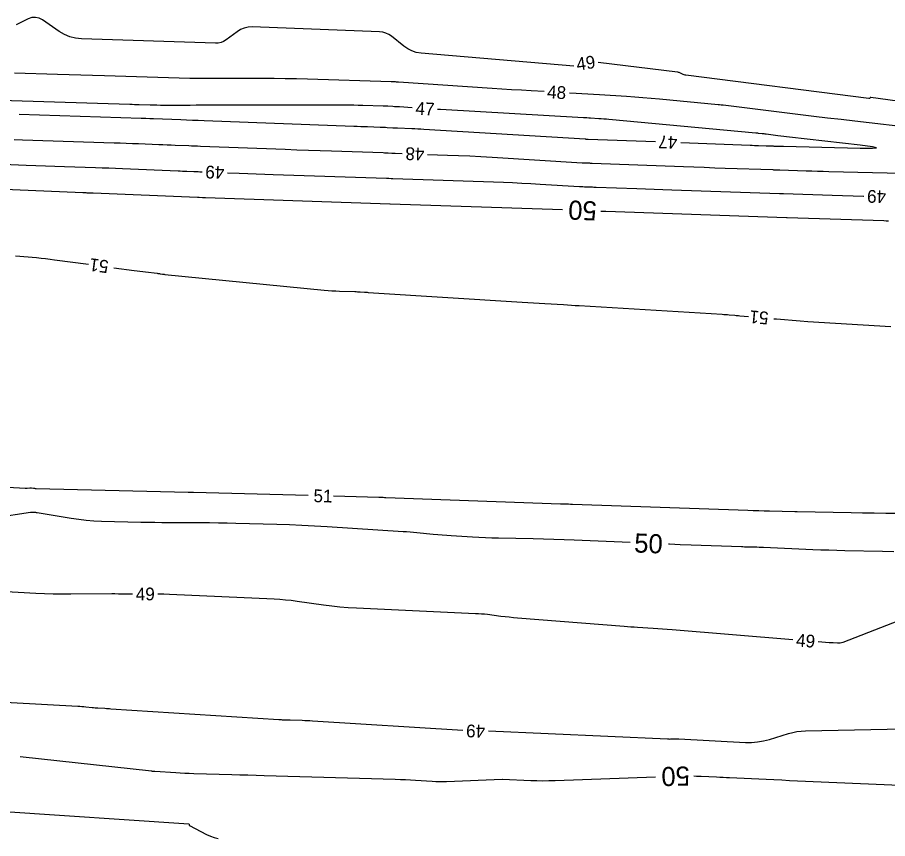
# Model space of a CAD drawing. Extents: x 2384780 to 2405861, y 547869 to 573706.
# Drawn here: x 2392231.5 to 2392368.2, y 552612.6 to 552741.6 of the extents above; entities that cross this region are included whole.
import ezdxf

# ---------------------------------------------------------------- set-up
doc = ezdxf.new("R2010")
doc.units = 0
doc.layers.add('Old_Level_60', color=7, linetype='Continuous')
doc.layers.add('Old_Level_61', color=7, linetype='Continuous')

msp = doc.modelspace()

# ---------------------------------------------------------------- linework, layer by layer
at = {"layer": 'Old_Level_60'}
for points in [[(2392318.946, 552733.94425), (2392294.92275, 552735.98225), (2392294.1865, 552736.098), (2392293.4915, 552736.3165), (2392292.8375, 552736.638), (2392292.22475, 552737.06225), (2392290.29025, 552738.616), (2392289.861, 552738.91), (2392289.40275, 552739.12575), (2392288.91525, 552739.26325), (2392288.3985, 552739.3225), (2392268.411, 552740.0835), (2392267.7685, 552740.05625), (2392267.1585, 552739.92475), (2392266.58075, 552739.68875), (2392266.03525, 552739.34825), (2392264.306, 552738.06525), (2392263.92425, 552737.82675), (2392263.51975, 552737.6605), (2392263.0925, 552737.567), (2392262.64275, 552737.54575), (2392241.6115, 552738.23625), (2392240.67325, 552738.3315), (2392239.77675, 552738.5545), (2392238.92225, 552738.9055), (2392238.1095, 552739.384), (2392235.48175, 552741.184), (2392234.94225, 552741.46825), (2392234.39075, 552741.59025), (2392233.8275, 552741.5495), (2392233.2525, 552741.34625), (2392231.35475, 552740.41675)], [(2392369.731, 552728.44225), (2392365.5835, 552729.002), (2392365.54375, 552729.0035), (2392365.50625, 552728.99725), (2392365.471, 552728.983), (2392365.438, 552728.961), (2392365.334, 552728.87575), (2392365.31075, 552728.86025), (2392365.28625, 552728.85025), (2392365.26, 552728.84575), (2392365.232, 552728.84675), (2392336.52225, 552732.51525), (2392336.382, 552732.53875), (2392336.245, 552732.573), (2392336.111, 552732.61825), (2392335.98025, 552732.674), (2392335.5585, 552732.874), (2392335.467, 552732.91275), (2392335.37325, 552732.94425), (2392335.27725, 552732.96775), (2392335.179, 552732.98375), (2392322.74, 552734.4965)], [(2392314.24625, 552729.93575), (2392312.199, 552730.05175), (2392310.679, 552730.13975), (2392309.1595, 552730.23175), (2392307.64025, 552730.32775), (2392306.121, 552730.42775), (2392291.4055, 552731.416), (2392291.28775, 552731.42375), (2392291.17025, 552731.43125), (2392291.0525, 552731.4385), (2392290.93475, 552731.44525), (2392290.55, 552731.467), (2392290.46775, 552731.47125), (2392290.38525, 552731.47525), (2392290.30275, 552731.4785), (2392290.22025, 552731.48125), (2392277.07925, 552731.87825), (2392275.3475, 552731.924), (2392273.61575, 552731.95625), (2392271.88375, 552731.975), (2392270.1515, 552731.98025), (2392262.928, 552731.97475), (2392262.4975, 552731.9745), (2392262.06725, 552731.97425), (2392261.63675, 552731.97375), (2392261.2065, 552731.9735), (2392259.8005, 552731.9725), (2392259.49925, 552731.9735), (2392259.19825, 552731.97675), (2392258.897, 552731.98225), (2392258.59575, 552731.99025), (2392245.204, 552732.3965), (2392243.36025, 552732.4525), (2392241.5165, 552732.50875), (2392239.673, 552732.565), (2392237.82925, 552732.62125), (2392231.0935, 552732.827)], [(2392293.51075, 552727.38425), (2392291.53, 552727.51725), (2392291.27875, 552727.53375), (2392291.0275, 552727.54975), (2392290.776, 552727.565), (2392290.5245, 552727.5795), (2392289.703, 552727.626), (2392289.527, 552727.63525), (2392289.35075, 552727.6435), (2392289.17475, 552727.6505), (2392288.9985, 552727.6565), (2392285.7645, 552727.75425), (2392285.0715, 552727.7725), (2392284.3785, 552727.78525), (2392283.68525, 552727.79275), (2392282.992, 552727.795), (2392261.4575, 552727.7785), (2392260.53475, 552727.77775), (2392259.61175, 552727.77725), (2392258.68875, 552727.7765), (2392257.76575, 552727.77575), (2392254.5175, 552727.77325), (2392253.98825, 552727.775), (2392253.459, 552727.78075), (2392252.92975, 552727.7905), (2392252.4005, 552727.8045), (2392250.67175, 552727.857), (2392250.3015, 552727.86825), (2392249.931, 552727.8795), (2392249.5605, 552727.89075), (2392249.19025, 552727.90225), (2392223.8225, 552728.67725)], [(2392372.96725, 552724.14875), (2392363.02575, 552725.288), (2392360.89575, 552725.53425), (2392358.76625, 552725.785), (2392356.63725, 552726.03975), (2392354.50875, 552726.299), (2392342.38, 552727.7885), (2392342.2995, 552727.7985), (2392342.219, 552727.808), (2392342.1385, 552727.8175), (2392342.058, 552727.827), (2392341.795, 552727.8575), (2392341.73875, 552727.86375), (2392341.68225, 552727.86975), (2392341.62575, 552727.8755), (2392341.56925, 552727.881), (2392332.37925, 552728.728), (2392331.081, 552728.8435), (2392329.78225, 552728.951), (2392328.48275, 552729.05), (2392327.1825, 552729.14125), (2392322.9345, 552729.42525), (2392322.024, 552729.485), (2392321.1135, 552729.54225), (2392320.20275, 552729.5975), (2392319.292, 552729.65), (2392318.23975, 552729.70975)], [(2392231.84125, 552726.37275), (2392250.9685, 552725.76425), (2392251.16, 552725.758), (2392251.35175, 552725.75125), (2392251.54325, 552725.74375), (2392251.735, 552725.736), (2392252.36075, 552725.70975), (2392252.495, 552725.70425), (2392252.629, 552725.69875), (2392252.76325, 552725.6935), (2392252.89725, 552725.6885), (2392257.1815, 552725.527), (2392258.0995, 552725.4925), (2392259.0175, 552725.458), (2392259.9355, 552725.4235), (2392260.8535, 552725.38875), (2392284.3775, 552724.50325), (2392284.91675, 552724.483), (2392285.456, 552724.4635), (2392285.9955, 552724.4445), (2392286.53475, 552724.42625), (2392288.50875, 552724.3595), (2392288.78025, 552724.3495), (2392289.0515, 552724.3375), (2392289.32275, 552724.32375), (2392289.594, 552724.30775), (2392290.4795, 552724.25325), (2392290.66925, 552724.24225), (2392290.859, 552724.2325), (2392291.049, 552724.22425), (2392291.239, 552724.217), (2392293.46525, 552724.142), (2392293.94225, 552724.12425), (2392294.419, 552724.10325), (2392294.89575, 552724.07875), (2392295.37225, 552724.05125), (2392320.71275, 552722.49325), (2392320.76, 552722.4905), (2392320.80725, 552722.488), (2392320.85425, 552722.486), (2392320.9015, 552722.48425), (2392321.05575, 552722.479), (2392321.08875, 552722.47775), (2392321.12175, 552722.47675), (2392321.15475, 552722.4755), (2392321.18775, 552722.47425), (2392331.742, 552722.07275)], [(2392335.73925, 552721.92075), (2392346.63, 552721.5065), (2392346.95125, 552721.4945), (2392347.2725, 552721.48275), (2392347.59375, 552721.4715), (2392347.915, 552721.4605), (2392349.102, 552721.42075), (2392349.25825, 552721.41575), (2392349.4145, 552721.411), (2392349.57075, 552721.40675), (2392349.727, 552721.40275), (2392350.2375, 552721.39025), (2392350.34675, 552721.3875), (2392350.45625, 552721.3845), (2392350.5655, 552721.38125), (2392350.67475, 552721.37775), (2392351.3125, 552721.35625), (2392351.44925, 552721.352), (2392351.58575, 552721.34775), (2392351.7225, 552721.344), (2392351.85925, 552721.34075), (2392363.88225, 552721.05475), (2392365.8165, 552721.03775), (2392366.4665, 552721.1095), (2392365.8325, 552721.27), (2392363.91425, 552721.519), (2392352.8065, 552722.79175), (2392352.34425, 552722.84525), (2392351.882, 552722.89975), (2392351.41975, 552722.955), (2392350.95775, 552723.01125), (2392349.12725, 552723.236), (2392348.9645, 552723.256), (2392348.80175, 552723.2755), (2392348.63875, 552723.29475), (2392348.47575, 552723.31375), (2392347.9435, 552723.3755), (2392347.8295, 552723.38825), (2392347.71525, 552723.4005), (2392347.601, 552723.412), (2392347.48675, 552723.423), (2392324.43025, 552725.548), (2392324.03225, 552725.5835), (2392323.634, 552725.6165), (2392323.2355, 552725.64675), (2392322.83675, 552725.67475), (2392321.53425, 552725.76175), (2392321.255, 552725.78025), (2392320.97575, 552725.79775), (2392320.69675, 552725.81475), (2392320.41725, 552725.83075), (2392297.97825, 552727.10125), (2392297.50275, 552727.12875)], [(2392231.04725, 552722.40725), (2392232.34875, 552722.36425), (2392246.716, 552721.90725), (2392247.67675, 552721.8755), (2392248.63725, 552721.84125), (2392249.59775, 552721.8045), (2392250.558, 552721.76525), (2392253.743, 552721.6315), (2392254.39125, 552721.60475), (2392255.0395, 552721.5785), (2392255.688, 552721.553), (2392256.33625, 552721.52825), (2392258.45425, 552721.4485), (2392258.908, 552721.4315), (2392259.362, 552721.41425), (2392259.81575, 552721.39725), (2392260.2695, 552721.38025), (2392273.6125, 552720.87775), (2392275.43125, 552720.81025), (2392277.25, 552720.7445), (2392279.06875, 552720.6805), (2392280.88775, 552720.61825), (2392289.00725, 552720.34425), (2392289.19175, 552720.3375), (2392289.37575, 552720.32925), (2392289.56, 552720.32), (2392289.74425, 552720.30925), (2392290.3455, 552720.272), (2392290.47425, 552720.26475), (2392290.60325, 552720.258), (2392290.73225, 552720.25225), (2392290.86125, 552720.2475), (2392291.95025, 552720.21075)], [(2392217.11775, 552719.0455), (2392232.93825, 552718.38325), (2392234.436, 552718.3225), (2392235.93425, 552718.26525), (2392237.43225, 552718.212), (2392238.93075, 552718.1625), (2392243.8255, 552718.00675), (2392244.87425, 552717.972), (2392245.923, 552717.93475), (2392246.97175, 552717.8945), (2392248.02025, 552717.852), (2392256.77325, 552717.484), (2392257.11175, 552717.47), (2392257.45, 552717.45625), (2392257.7885, 552717.443), (2392258.127, 552717.43), (2392259.2325, 552717.3885), (2392259.46925, 552717.3795), (2392259.70625, 552717.37075), (2392259.94325, 552717.36175), (2392260.18, 552717.35275), (2392260.5555, 552717.33875)], [(2392295.948, 552720.076), (2392299.067, 552719.97075), (2392300.825, 552719.90525), (2392302.5825, 552719.82775), (2392304.3395, 552719.738), (2392306.096, 552719.636), (2392320.25575, 552718.7655), (2392320.4095, 552718.7565), (2392320.56325, 552718.74875), (2392320.71725, 552718.742), (2392320.871, 552718.73625), (2392321.37375, 552718.71925), (2392321.4815, 552718.7155), (2392321.58925, 552718.7115), (2392321.697, 552718.70775), (2392321.80475, 552718.70375), (2392336.12025, 552718.15925), (2392337.7665, 552718.0975), (2392339.4125, 552718.03775), (2392341.05875, 552717.97975), (2392342.705, 552717.92375), (2392350.172, 552717.67375), (2392350.27975, 552717.6705), (2392350.38775, 552717.66725), (2392350.49575, 552717.66425), (2392350.6035, 552717.6615), (2392350.956, 552717.65275), (2392351.0315, 552717.65075), (2392351.107, 552717.64875), (2392351.1825, 552717.6465), (2392351.258, 552717.644), (2392355.40075, 552717.5055), (2392356.28825, 552717.47675), (2392357.176, 552717.45025), (2392358.064, 552717.426), (2392358.95175, 552717.40375), (2392374.98775, 552717.0225)], [(2392264.5525, 552717.18825), (2392266.3845, 552717.11925), (2392267.714, 552717.06975), (2392269.0435, 552717.02175), (2392270.37325, 552716.975), (2392271.703, 552716.9295), (2392289.506, 552716.329), (2392289.603, 552716.3255), (2392289.70025, 552716.321), (2392289.79725, 552716.31625), (2392289.8945, 552716.3105), (2392290.2115, 552716.291), (2392290.27925, 552716.287), (2392290.34725, 552716.2835), (2392290.41525, 552716.2805), (2392290.48325, 552716.278), (2392307.873, 552715.69125), (2392309.3105, 552715.63775), (2392310.74725, 552715.5745), (2392312.1835, 552715.501), (2392313.6195, 552715.41775), (2392319.79875, 552715.03775), (2392320.059, 552715.02275), (2392320.3195, 552715.0095), (2392320.58, 552714.998), (2392320.8405, 552714.98825), (2392321.692, 552714.95925), (2392321.8745, 552714.953), (2392322.05675, 552714.9465), (2392322.23925, 552714.94), (2392322.42175, 552714.933), (2392328.81325, 552714.69), (2392330.18275, 552714.63875), (2392331.5525, 552714.589), (2392332.92225, 552714.54075), (2392334.292, 552714.494), (2392351.24175, 552713.927), (2392351.3015, 552713.925), (2392351.361, 552713.92325), (2392351.4205, 552713.9215), (2392351.48, 552713.92), (2392351.6745, 552713.91525), (2392351.71625, 552713.91425), (2392351.758, 552713.913), (2392351.79975, 552713.91175), (2392351.84125, 552713.9105), (2392359.48875, 552713.6545), (2392361.1275, 552713.60175), (2392362.7665, 552713.55275), (2392364.4055, 552713.508), (2392364.4815, 552713.506)], [(2392231.24525, 552704.1535), (2392234.54925, 552703.848), (2392235.25675, 552703.77875), (2392235.9635, 552703.70225), (2392236.6695, 552703.6185), (2392237.37475, 552703.5275), (2392242.7235, 552702.808)], [(2392246.688, 552702.275), (2392249.88675, 552701.84475), (2392250.3295, 552701.78575), (2392250.7725, 552701.7285), (2392251.21575, 552701.6725), (2392251.659, 552701.618), (2392253.4935, 552701.39575), (2392253.611, 552701.38075), (2392253.72825, 552701.3645), (2392253.84525, 552701.34725), (2392253.96225, 552701.3285), (2392254.34375, 552701.265), (2392254.4255, 552701.252), (2392254.50775, 552701.2405), (2392254.58975, 552701.2305), (2392254.67225, 552701.22175), (2392279.71925, 552698.76), (2392280.31975, 552698.70575), (2392280.921, 552698.661), (2392281.52275, 552698.6255), (2392282.12525, 552698.5995), (2392284.521, 552698.51525), (2392284.7295, 552698.50725), (2392284.93825, 552698.49775), (2392285.14675, 552698.48725), (2392285.35525, 552698.47525), (2392286.036, 552698.434), (2392286.182, 552698.425), (2392286.328, 552698.416), (2392286.47375, 552698.407), (2392286.61975, 552698.39775), (2392310.8225, 552696.86725), (2392311.712, 552696.8115), (2392312.60175, 552696.756), (2392313.49125, 552696.70125), (2392314.381, 552696.64725), (2392317.28725, 552696.47125), (2392317.91, 552696.4335), (2392318.533, 552696.39575), (2392319.15575, 552696.35775), (2392319.7785, 552696.32), (2392342.22075, 552694.95325), (2392342.49475, 552694.9355), (2392342.76875, 552694.916), (2392343.04275, 552694.89475), (2392343.3165, 552694.8715), (2392344.21025, 552694.79275), (2392344.402, 552694.77575), (2392344.5935, 552694.75875), (2392344.785, 552694.742), (2392344.9765, 552694.725), (2392346.3655, 552694.6025)], [(2392350.35, 552694.25125), (2392350.7455, 552694.21625), (2392351.982, 552694.11125), (2392353.21925, 552694.0145), (2392354.457, 552693.9255), (2392355.69525, 552693.84475), (2392368.702, 552693.038)], [(2392277.1785, 552666.47575), (2392259.21875, 552666.9365), (2392259.135, 552666.9385), (2392259.0515, 552666.94), (2392258.96775, 552666.941), (2392258.884, 552666.9415), (2392258.6105, 552666.94275), (2392258.552, 552666.94325), (2392258.4935, 552666.944), (2392258.43475, 552666.945), (2392258.37625, 552666.94625), (2392234.46875, 552667.55475), (2392234.37175, 552667.559), (2392234.275, 552667.5665), (2392234.1785, 552667.5775), (2392234.0825, 552667.592), (2392233.769, 552667.6445), (2392233.70175, 552667.653), (2392233.6345, 552667.6565), (2392233.56725, 552667.65475), (2392233.49975, 552667.6475), (2392233.09925, 552667.59025), (2392233.0135, 552667.58), (2392232.92725, 552667.57425), (2392232.841, 552667.57275), (2392232.7545, 552667.5755), (2392203.68075, 552669.25225)], [(2392369.75775, 552663.664), (2392367.93125, 552663.67825), (2392366.105, 552663.6985), (2392364.27875, 552663.725), (2392362.4525, 552663.75725), (2392354.0095, 552663.9215), (2392353.97, 552663.92225), (2392353.9305, 552663.9235), (2392353.89125, 552663.92475), (2392353.85175, 552663.9265), (2392353.72325, 552663.93225), (2392353.69575, 552663.93325), (2392353.668, 552663.93425), (2392353.6405, 552663.935), (2392353.613, 552663.93575), (2392349.65525, 552664.01475), (2392348.80725, 552664.03325), (2392347.95925, 552664.05525), (2392347.11125, 552664.08025), (2392346.2635, 552664.10875), (2392318.73125, 552665.085), (2392318.64525, 552665.08825), (2392318.55925, 552665.0915), (2392318.473, 552665.095), (2392318.387, 552665.09875), (2392318.106, 552665.11125), (2392318.046, 552665.11375), (2392317.98575, 552665.11575), (2392317.9255, 552665.11725), (2392317.86525, 552665.1185), (2392317.29925, 552665.1285), (2392317.17775, 552665.13075), (2392317.0565, 552665.13375), (2392316.93525, 552665.13725), (2392316.814, 552665.14125), (2392289.42425, 552666.1135), (2392289.36625, 552666.11625), (2392289.30825, 552666.1195), (2392289.2505, 552666.12375), (2392289.1925, 552666.129), (2392289.00375, 552666.14775), (2392288.96325, 552666.1515), (2392288.923, 552666.155), (2392288.88225, 552666.158), (2392288.84175, 552666.16075), (2392288.561, 552666.179), (2392288.50075, 552666.18275), (2392288.4405, 552666.18575), (2392288.38025, 552666.188), (2392288.32, 552666.19), (2392281.17725, 552666.37325)], [(2392249.62075, 552650.99475), (2392248.08575, 552650.97975), (2392247.91575, 552650.97925), (2392247.74575, 552650.98125), (2392247.576, 552650.9855), (2392247.40625, 552650.992), (2392246.85175, 552651.0175), (2392246.73275, 552651.02225), (2392246.614, 552651.02525), (2392246.495, 552651.0265), (2392246.376, 552651.02625), (2392239.93825, 552650.96475), (2392238.559, 552650.96325), (2392237.1805, 552650.9845), (2392235.80225, 552651.02875), (2392234.42475, 552651.096), (2392218.6555, 552651.99725)], [(2392353.327, 552643.83475), (2392334.34125, 552645.38575), (2392333.5975, 552645.4445), (2392332.8535, 552645.49975), (2392332.10925, 552645.551), (2392331.36475, 552645.59875), (2392328.9325, 552645.748), (2392328.41125, 552645.78125), (2392327.89025, 552645.817), (2392327.3695, 552645.855), (2392326.84875, 552645.8955), (2392310.089, 552647.23525), (2392309.43375, 552647.29125), (2392308.779, 552647.3545), (2392308.125, 552647.425), (2392307.472, 552647.5025), (2392305.3395, 552647.768), (2392304.882, 552647.82025), (2392304.424, 552647.86375), (2392303.965, 552647.898), (2392303.5055, 552647.92325), (2392284.77575, 552648.771), (2392283.48575, 552648.845), (2392282.19875, 552648.95025), (2392280.91475, 552649.0865), (2392279.6335, 552649.254), (2392275.453, 552649.852), (2392274.556, 552649.96925), (2392273.65725, 552650.065), (2392272.75625, 552650.13925), (2392271.85325, 552650.19175), (2392255.4115, 552650.95175), (2392254.52775, 552650.9865), (2392253.6435, 552651.00875), (2392253.62075, 552651.009)], [(2392375.815, 552649.12325), (2392361.17425, 552643.41075), (2392360.9715, 552643.34375), (2392360.76525, 552643.3), (2392360.5555, 552643.279), (2392360.342, 552643.281), (2392359.639, 552643.325), (2392359.4885, 552643.33475), (2392359.338, 552643.34525), (2392359.1875, 552643.3565), (2392359.037, 552643.36825), (2392357.31375, 552643.509)], [(2392213.37025, 552634.89325), (2392241.0165, 552633.41), (2392241.33125, 552633.39075), (2392241.6455, 552633.36725), (2392241.95925, 552633.339), (2392242.273, 552633.3065), (2392243.2965, 552633.1925), (2392243.516, 552633.16975), (2392243.73575, 552633.14975), (2392243.95575, 552633.13275), (2392244.176, 552633.119), (2392245.2735, 552633.057), (2392245.50875, 552633.04375), (2392245.744, 552633.02975), (2392245.979, 552633.01525), (2392246.214, 552633.00025), (2392272.58825, 552631.29425), (2392272.76575, 552631.28375), (2392272.94325, 552631.2745), (2392273.12075, 552631.267), (2392273.29825, 552631.26125), (2392273.87875, 552631.2445), (2392274.003, 552631.24075), (2392274.1275, 552631.23725), (2392274.25175, 552631.23375), (2392274.37625, 552631.23), (2392276.26725, 552631.1755), (2392276.67225, 552631.162), (2392277.07725, 552631.14525), (2392277.48225, 552631.12475), (2392277.88675, 552631.101), (2392301.51375, 552629.60475)], [(2392305.5085, 552629.504), (2392305.51725, 552629.5035), (2392305.533, 552629.50275), (2392333.6545, 552628.24475), (2392333.82725, 552628.2385), (2392334.00025, 552628.236), (2392334.17325, 552628.237), (2392334.34625, 552628.24125), (2392334.91125, 552628.261), (2392335.03225, 552628.264), (2392335.15325, 552628.26425), (2392335.27425, 552628.26175), (2392335.39525, 552628.25675), (2392345.8595, 552627.7125), (2392346.81975, 552627.704), (2392347.76975, 552627.779), (2392348.7095, 552627.93725), (2392349.63875, 552628.17875), (2392352.658, 552629.10425), (2392353.30875, 552629.2795), (2392353.96675, 552629.40825), (2392354.63225, 552629.49075), (2392355.305, 552629.52675), (2392373.2665, 552629.86925)], [(2392228.7055, 552616.91925), (2392258.45475, 552614.889), (2392258.485, 552614.8825), (2392258.5065, 552614.868), (2392258.519, 552614.84525), (2392258.52275, 552614.8145), (2392258.52075, 552614.70075), (2392258.523, 552614.678), (2392258.53075, 552614.6585), (2392258.544, 552614.6425), (2392258.563, 552614.6295), (2392261.26, 552613.222), (2392261.847, 552612.95075), (2392262.45175, 552612.74), (2392263.07425, 552612.59)]]:
    msp.add_lwpolyline(points, dxfattribs=at)
at = {"layer": 'Old_Level_61'}
for points in [[(2392217.2305, 552715.1105), (2392241.79625, 552714.08225), (2392241.95925, 552714.0755), (2392242.12225, 552714.06925), (2392242.28525, 552714.0635), (2392242.44825, 552714.058), (2392242.98075, 552714.04125), (2392243.09475, 552714.0375), (2392243.209, 552714.03325), (2392243.323, 552714.029), (2392243.437, 552714.02425), (2392259.8035, 552713.3365), (2392259.832, 552713.3355), (2392259.8605, 552713.33425), (2392259.889, 552713.333), (2392259.9175, 552713.332), (2392260.01075, 552713.3285), (2392260.0305, 552713.32775), (2392260.0505, 552713.327), (2392260.0705, 552713.32625), (2392260.0905, 552713.3255), (2392260.61325, 552713.30575), (2392260.72525, 552713.30175), (2392260.83725, 552713.2975), (2392260.94925, 552713.29375), (2392261.06125, 552713.28975), (2392290.0045, 552712.31375), (2392290.0145, 552712.31325), (2392290.0245, 552712.313), (2392290.0345, 552712.3125), (2392290.04475, 552712.31175), (2392290.07725, 552712.30975), (2392290.0845, 552712.3095), (2392290.0915, 552712.309), (2392290.0985, 552712.30875), (2392290.1055, 552712.3085), (2392317.16075, 552711.39575)], [(2392323.15575, 552711.158), (2392323.447, 552711.147), (2392323.56975, 552711.14225), (2392323.6925, 552711.138), (2392323.815, 552711.1335), (2392323.93775, 552711.1295), (2392352.31175, 552710.18), (2392352.323, 552710.1795), (2392352.33425, 552710.17925), (2392352.34525, 552710.179), (2392352.3565, 552710.1785), (2392352.39325, 552710.17775), (2392352.401, 552710.1775), (2392352.409, 552710.17725), (2392352.41675, 552710.177), (2392352.4245, 552710.17675), (2392367.59925, 552709.66925), (2392367.97775, 552709.657), (2392368.35625, 552709.64575)], [(2392327.78475, 552659.08175), (2392318.99775, 552659.47075), (2392317.38725, 552659.5365), (2392315.776, 552659.5915), (2392314.16475, 552659.63575), (2392312.553, 552659.66925), (2392307.06825, 552659.7645), (2392306.04975, 552659.788), (2392305.032, 552659.82375), (2392304.01475, 552659.871), (2392302.998, 552659.9305), (2392299.67725, 552660.14375), (2392298.96575, 552660.1925), (2392298.255, 552660.24725), (2392297.5445, 552660.30775), (2392296.83475, 552660.3745), (2392294.29225, 552660.6245), (2392293.74725, 552660.67575), (2392293.202, 552660.7225), (2392292.65625, 552660.7645), (2392292.11025, 552660.80225), (2392280.16175, 552661.5765), (2392278.19625, 552661.69425), (2392276.23, 552661.79275), (2392274.263, 552661.872), (2392272.295, 552661.932), (2392265.86475, 552662.097), (2392264.48675, 552662.12875), (2392263.10875, 552662.153), (2392261.7305, 552662.17025), (2392260.35225, 552662.18), (2392255.28425, 552662.20225), (2392254.19825, 552662.21), (2392253.11225, 552662.22325), (2392252.0265, 552662.2425), (2392250.94075, 552662.26725), (2392244.75725, 552662.42475), (2392243.558, 552662.47625), (2392242.363, 552662.56975), (2392241.172, 552662.70525), (2392239.985, 552662.88275), (2392234.663, 552663.77425), (2392234.55875, 552663.7895), (2392234.4545, 552663.8005), (2392234.3495, 552663.8075), (2392234.24425, 552663.81), (2392233.90025, 552663.811), (2392233.8265, 552663.81), (2392233.753, 552663.80625), (2392233.67975, 552663.79975), (2392233.6065, 552663.79075), (2392228.03575, 552662.992)], [(2392369.18475, 552657.6595), (2392367.38425, 552657.69475), (2392361.5025, 552657.809), (2392360.24225, 552657.8375), (2392358.98225, 552657.87375), (2392357.7225, 552657.918), (2392356.463, 552657.97), (2392348.69475, 552658.31525), (2392348.352, 552658.32925), (2392348.00925, 552658.3415), (2392347.6665, 552658.3515), (2392347.3235, 552658.35925), (2392346.20325, 552658.38175), (2392345.963, 552658.387), (2392345.723, 552658.39325), (2392345.483, 552658.40025), (2392345.243, 552658.40825), (2392337.3375, 552658.68875), (2392335.6435, 552658.7505), (2392333.9495, 552658.81625), (2392333.77925, 552658.82325)], [(2392231.95725, 552625.50825), (2392252.5745, 552623.21475), (2392252.62725, 552623.20925), (2392252.68025, 552623.2045), (2392252.733, 552623.2005), (2392252.786, 552623.19725), (2392252.959, 552623.1875), (2392252.996, 552623.18525), (2392253.033, 552623.183), (2392253.07025, 552623.18075), (2392253.10725, 552623.1785), (2392256.40175, 552622.96525), (2392257.108, 552622.92275), (2392257.8145, 552622.88675), (2392258.52125, 552622.85675), (2392259.22825, 552622.83325), (2392265.1905, 552622.66125), (2392266.468, 552622.6245), (2392267.74575, 552622.5875), (2392269.02325, 552622.55075), (2392270.301, 552622.514), (2392290.88575, 552621.92025), (2392291.68575, 552621.89375), (2392292.48525, 552621.8605), (2392293.2845, 552621.82), (2392294.08325, 552621.773), (2392296.6925, 552621.60775), (2392297.25175, 552621.57975), (2392297.811, 552621.566), (2392298.3705, 552621.567), (2392298.93025, 552621.58275), (2392307.667, 552621.939), (2392307.672, 552621.93925), (2392307.677, 552621.93925), (2392307.682, 552621.939), (2392307.687, 552621.93875), (2392307.70325, 552621.93775), (2392307.70675, 552621.93775), (2392307.71025, 552621.9375), (2392307.71375, 552621.93725), (2392307.71725, 552621.937), (2392312.1635, 552621.73825), (2392313.11625, 552621.705), (2392314.06925, 552621.691), (2392315.02225, 552621.69575), (2392315.97525, 552621.7195), (2392331.77325, 552622.2715)], [(2392337.77025, 552622.43175), (2392338.19, 552622.42375), (2392338.926, 552622.3935), (2392341.3305, 552622.26825), (2392341.84575, 552622.242), (2392342.361, 552622.2165), (2392342.8765, 552622.192), (2392343.39175, 552622.16825), (2392349.11875, 552621.9095), (2392350.346, 552621.854), (2392351.573, 552621.79875), (2392352.80025, 552621.74325), (2392354.0275, 552621.68775), (2392370.13625, 552620.96025)]]:
    msp.add_lwpolyline(points, dxfattribs=at)

# ---------------------------------------------------------------- texts
at = {"layer": 'Old_Level_60'}
for s, rotation, p in [('49', 8.2814, (2392319.47075, 552733.22875)), ('48', 356.7598528, (2392314.685, 552728.90925)), ('47', 356.3370111, (2392294.0125, 552726.34475)), ('47', 177.8217806, (2392335.2105, 552722.9415)), ('48', 178.0677167, (2392295.48575, 552721.092)), ('49', 177.8438333, (2392264.07075, 552718.207)), ('49', 178.6103222, (2392367.985, 552714.4205)), ('51', 172.3401167, (2392245.96275, 552703.3815)), ('51', 174.9604056, (2392349.575, 552695.3235)), ('51', 358.5304611, (2392278.01875, 552665.45375)), ('49', 0.2066306, (2392250.144, 552650.00875)), ('49', 355.330025, (2392353.76375, 552642.79575)), ('49', 178.553925, (2392305.01475, 552630.4415))]:
    msp.add_text(s, height=2, rotation=rotation, dxfattribs=at).set_placement(p)
at = {"layer": 'Old_Level_61'}
for rotation, p in [(177.7297111, (2392322.57725, 552712.6685)), (357.5310806, (2392328.3575, 552657.5525)), (181.5313194, (2392337.0925, 552623.93875))]:
    msp.add_text('50', height=3, rotation=rotation, dxfattribs=at).set_placement(p)

doc.saveas('drawing.dxf')
